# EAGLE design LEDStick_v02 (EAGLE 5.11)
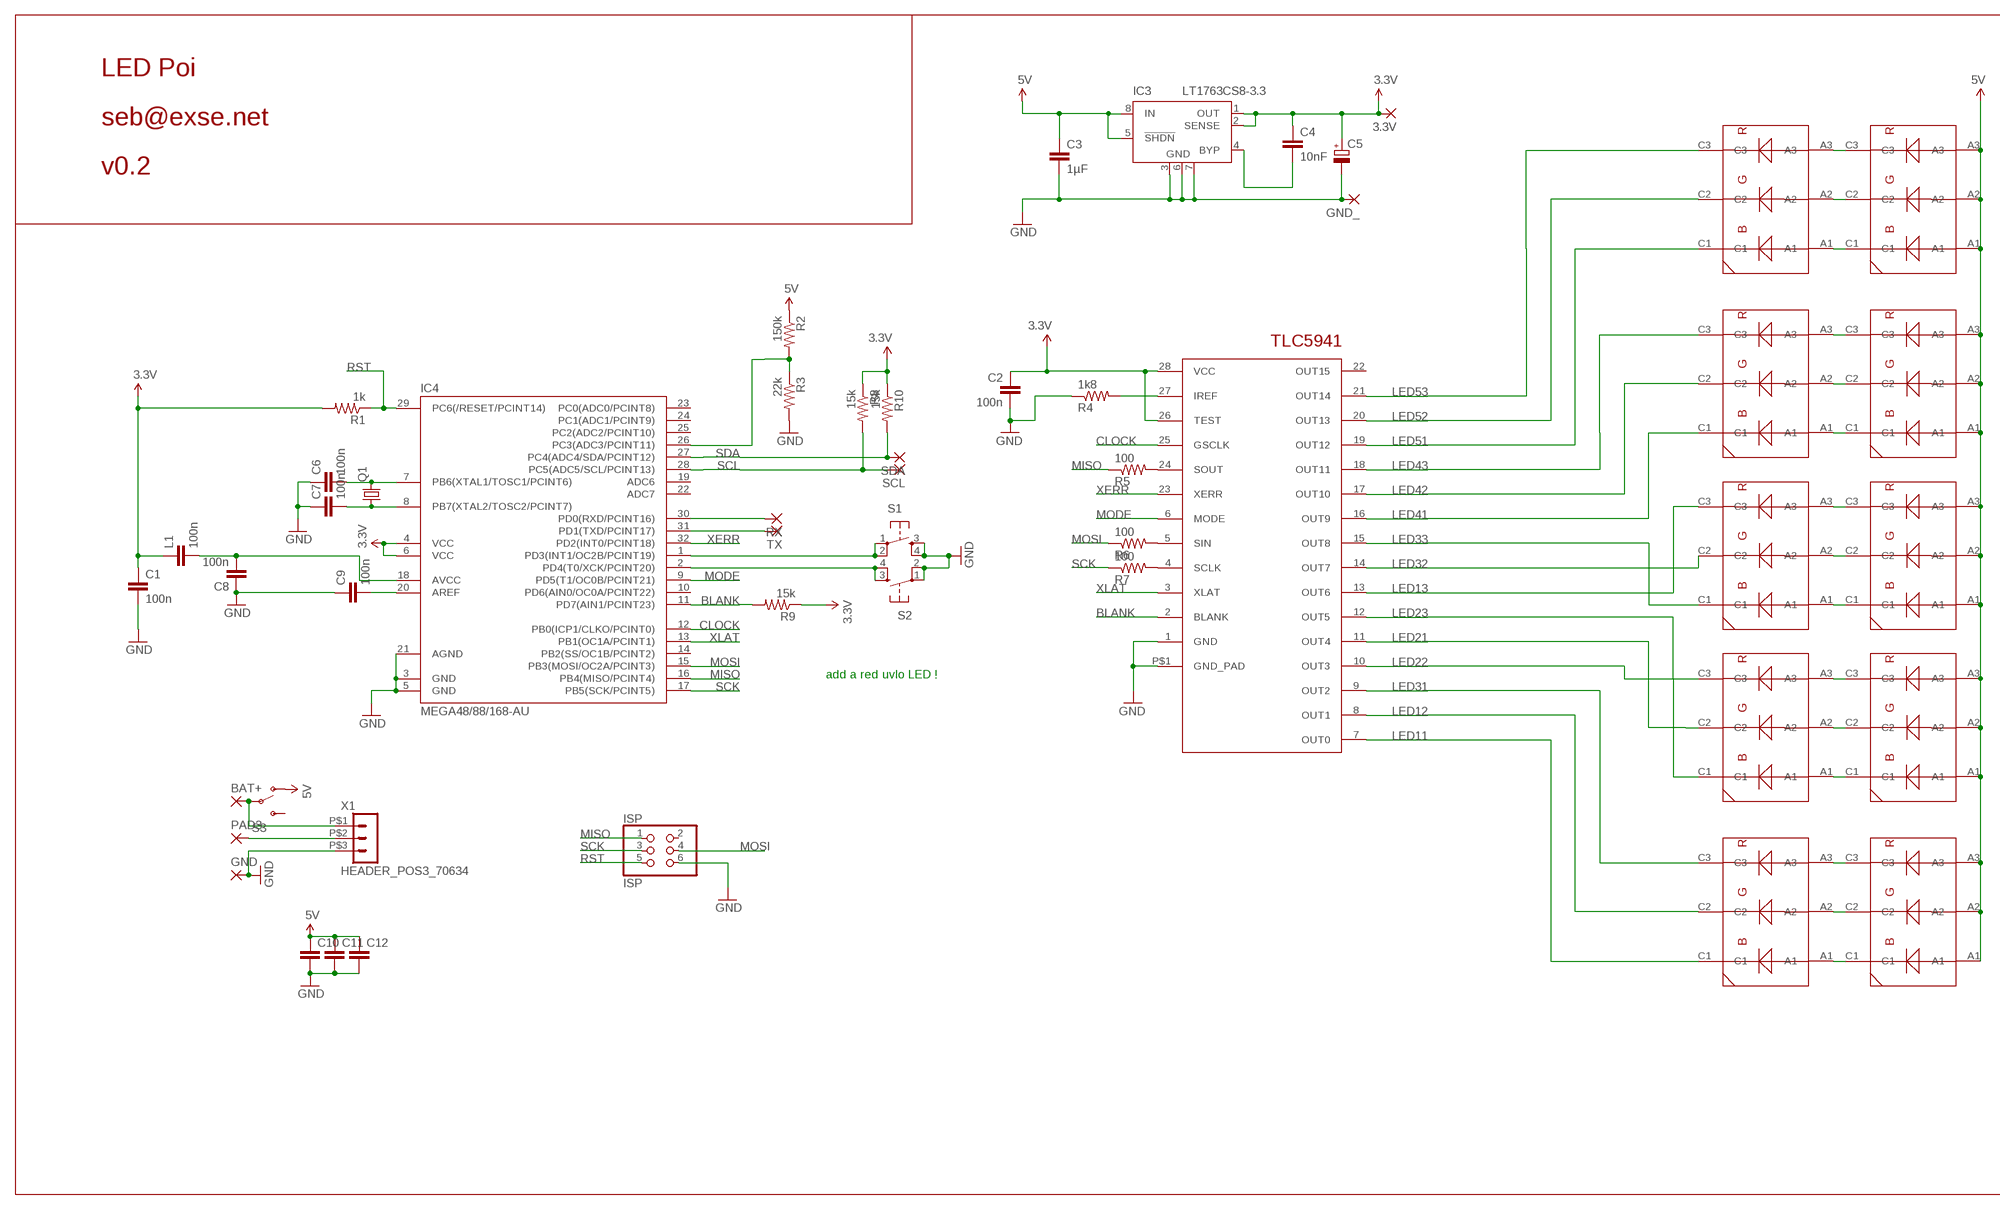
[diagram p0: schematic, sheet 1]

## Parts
3.3V  SMD2  [SMD1,27-2,54]
BAT+  SMD5  [SMD2,54-5,08]
C1  100n  CAP0805  [0805]
C2  100n  CAP0805  [0805]
C3  1µF  CAP0805  [0805]
C4  10nF  CAP0805  [0805]
C5  CPOL-EUSMCC  [SMC_C]
C6  100n  CAP0805  [0805]
C7  100n  CAP0805  [0805]
C8  100n  CAP0805  [0805]
C9  100n  CAP0805  [0805]
C10  C-EUC1210K  [C1210K]
C11  C-EUC1210K  [C1210K]
C12  C-EUC1210K  [C1210K]
D1  OSRAM_LRTB_GFTGSMALL  [PLCC-6_SMALL]
D2  OSRAM_LRTB_GFTGSMALL  [PLCC-6_SMALL]
D3  OSRAM_LRTB_GFTGSMALL  [PLCC-6_SMALL]
D4  OSRAM_LRTB_GFTGSMALL  [PLCC-6_SMALL]
D5  OSRAM_LRTB_GFTGSMALL  [PLCC-6_SMALL]
D6  OSRAM_LRTB_GFTGSMALL  [PLCC-6_SMALL]
D7  OSRAM_LRTB_GFTGSMALL  [PLCC-6_SMALL]
D8  OSRAM_LRTB_GFTGSMALL  [PLCC-6_SMALL]
D9  OSRAM_LRTB_GFTGSMALL  [PLCC-6_SMALL]
D10  OSRAM_LRTB_GFTGSMALL  [PLCC-6_SMALL]
GND  SMD5  [SMD2,54-5,08]
GND_  SMD2  [SMD1,27-2,54]
IC2  TLC5941  [SSOP28]
IC3  LT1763CS8-3.3  [SOIC8]
IC4  MEGA48/88/168-AU  [TQFP32-08]
ISP  ISP  PINHD-2X03_2.54  [2X03]
L1  100n  CAP0805  [0805]
PAD3  SMD5  [SMD2,54-5,08]
Q1  X22-OSCILLATOR  [X22]
R1  1k  RESISTOR  [0805]
R2  150k  RESISTOR  [0805]
R3  22k  RESISTOR  [0805]
R4  1k8  RESISTOR  [0805]
R5  100  RESISTOR  [0805]
R6  100  RESISTOR  [0805]
R7  100  RESISTOR  [0805]
R8  15k  RESISTOR  [0805]
R9  15k  RESISTOR  [0805]
R10  15k  RESISTOR  [0805]
RX  SMD2  [SMD1,27-2,54]
S1  LSH  [LSH]
S2  LSH  [LSH]
S3  SWITCH-SPSTPTH_LOCK  [SWITCH-SPDT_LOCK.007S]
SCL  SMD2  [SMD1,27-2,54]
SDA  SMD2  [SMD1,27-2,54]
TX  SMD2  [SMD1,27-2,54]
X1  HEADER_POS3_70634  [70634-POS3]

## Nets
3.3V: 3.3V.1(P) C1.1 C2.1 C4.1 C5.+ IC2.26(TEST) IC2.28(VCC) IC3.1(OUT) IC3.2(SENSE) IC4.4(VCC) IC4.6(VCC) L1.1 R1.2 R8.1 R9.1 R10.1
5V: C3.1 C10.1 C11.1 C12.1 D1.A1 D1.A2 D1.A3 D3.A1 D3.A2 D3.A3 D5.A1 D5.A2 D5.A3 D7.A1 D7.A2 D7.A3 D9.A1 D9.A2 D9.A3 IC3.5(!SHDN) IC3.8(IN) R2.1 S3.1(O)
BLANK: IC2.2(BLANK) IC4.11(PD7(AIN1/PCINT23)) R9.2
CLOCK: IC2.25(GSCLK) IC4.12(PB0(ICP1/CLKO/PCINT0))
GND: C1.2 C2.2 C3.2 C5.- C6.1 C7.1 C8.1 C9.1 C10.2 C11.2 C12.2 GND.1(P) GND_.1(P) IC2.1(GND) IC2.P$1(GND_PAD) IC3.3(GND) IC3.6(GND) IC3.7(GND) IC4.3(GND) IC4.5(GND) IC4.21(AGND) ISP.6 R3.2 R4.1 S1.3 S1.4 S2.1 S2.2 X1.P$3
LED11: D10.C1 IC2.7(OUT0)
LED12: D10.C2 IC2.8(OUT1)
LED13: D6.C3 IC2.13(OUT6)
LED21: D8.C2 IC2.11(OUT4)
LED22: D8.C3 IC2.10(OUT3)
LED23: D8.C1 IC2.12(OUT5)
LED31: D10.C3 IC2.9(OUT2)
LED32: D6.C2 IC2.14(OUT7)
LED33: D6.C1 IC2.15(OUT8)
LED41: D4.C1 IC2.16(OUT9)
LED42: D4.C2 IC2.17(OUT10)
LED43: D4.C3 IC2.18(OUT11)
LED51: D2.C1 IC2.19(OUT12)
LED52: D2.C2 IC2.20(OUT13)
LED53: D2.C3 IC2.21(OUT14)
MISO: IC4.16(PB4(MISO/PCINT4)) ISP.1 R5.1
MODE: IC2.6(MODE) IC4.9(PD5(T1/OC0B/PCINT21))
MOSI: IC4.15(PB3(MOSI/OC2A/PCINT3)) ISP.4 R6.1
N$1: IC2.24(SOUT) R5.2
N$2: C4.2 IC3.4(BYP)
N$3: C6.2 IC4.7(PB6(XTAL1/TOSC1/PCINT6)) Q1.3
N$4: IC2.5(SIN) R6.2
N$5: IC2.4(SCLK) R7.2
N$6: C7.2 IC4.8(PB7(XTAL2/TOSC2/PCINT7)) Q1.1
N$7: D1.C3 D2.A3
N$8: D1.C2 D2.A2
N$9: D1.C1 D2.A1
N$10: D3.C3 D4.A3
N$11: D3.C2 D4.A2
N$12: D3.C1 D4.A1
N$13: IC2.27(IREF) R4.2
N$14: D5.C3 D6.A3
N$15: D5.C2 D6.A2
N$16: D5.C1 D6.A1
N$17: D7.C3 D8.A3
N$18: D7.C2 D8.A2
N$19: D7.C1 D8.A1
N$20: D9.C3 D10.A3
N$21: D9.C2 D10.A2
N$22: D9.C1 D10.A1
N$23: IC4.1(PD3(INT1/OC2B/PCINT19)) S1.1 S1.2
N$24: IC4.2(PD4(T0/XCK/PCINT20)) S2.3 S2.4
N$25: IC4.26(PC3(ADC3/PCINT11)) R2.2 R3.1
N$26: BAT+.1(P) S3.2(P) X1.P$1
N$27: C8.2 IC4.18(AVCC) L1.2
N$28: C9.2 IC4.20(AREF)
N$29: PAD3.1(P) X1.P$2
N$31: IC4.30(PD0(RXD/PCINT16)) RX.1(P)
N$32: IC4.31(PD1(TXD/PCINT17)) TX.1(P)
RST: IC4.29(PC6(/RESET/PCINT14)) ISP.5 R1.1
SCK: IC4.17(PB5(SCK/PCINT5)) ISP.3 R7.1
SCL: IC4.28(PC5(ADC5/SCL/PCINT13)) R8.2 SCL.1(P)
SDA: IC4.27(PC4(ADC4/SDA/PCINT12)) R10.2 SDA.1(P)
XERR: IC2.23(XERR) IC4.32(PD2(INT0/PCINT18))
XLAT: IC2.3(XLAT) IC4.13(PB1(OC1A/PCINT1))
Unconnected: IC2.22(OUT15) IC4.10(PD6(AIN0/OC0A/PCINT22)) IC4.14(PB2(SS/OC1B/PCINT2)) IC4.19(ADC6) IC4.22(ADC7) IC4.23(PC0(ADC0/PCINT8)) IC4.24(PC1(ADC1/PCINT9)) IC4.25(PC2(ADC2/PCINT10)) ISP.2 S3.3(S)

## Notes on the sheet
- LED Poi
- seb@exse.net
- v0.2
- add a red uvlo LED !

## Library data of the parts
3.3V GND_ RX SCL SDA TX = wirepad:SMD2: SMD PAD
BAT+ GND PAD3 = wirepad:SMD5: SMD PAD
C1-C4 C6-C9 L1 = SparkFun:CAP: Capacitor
C5 = resistor:CPOL-EU: POLARIZED CAPACITOR, European symbol
C10-C12 = rcl:C-EU: CAPACITOR, European symbol
D1-D10 = seb:OSRAM_LRTB_GFTG
IC2 = tlc:TLC5941
IC3 = linear-technology:LT1763CS8: 500mA, Low Noise, LDO Micropower Regulators Source: http://cds.linear.com/docs/Datasheet/1763ff.pdf
IC4 = avr-7:MEGA48/88/168
ISP = pinhead-2:PINHD-2X03: PIN HEADER
Q1 = seb:X22-OSCILLATOR
R1-R10 = SparkFun:RESISTOR: Resistor
S1 S2 = switch-tact:LSH
S3 = SparkFun:SWITCH-SPST: SPST Switch Simple slide switch. Spark Fun Electronics SKU : COM-00102
X1 = con-molex-c-grid-sl:HEADER_POS3_?: Molex -C-Grid® / SL Series connector Wire-to-Board 2.54 mm (0.100") pitch header, 3 positions.

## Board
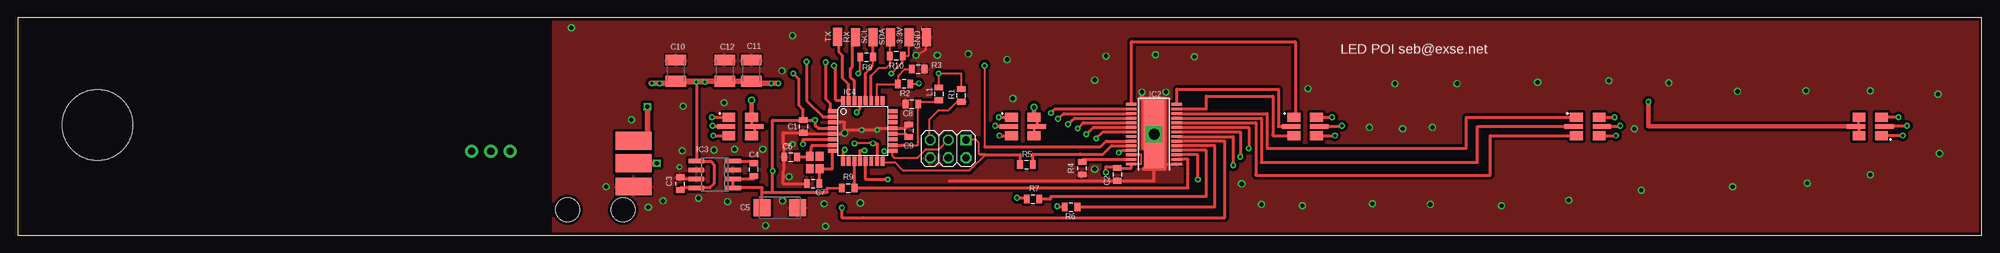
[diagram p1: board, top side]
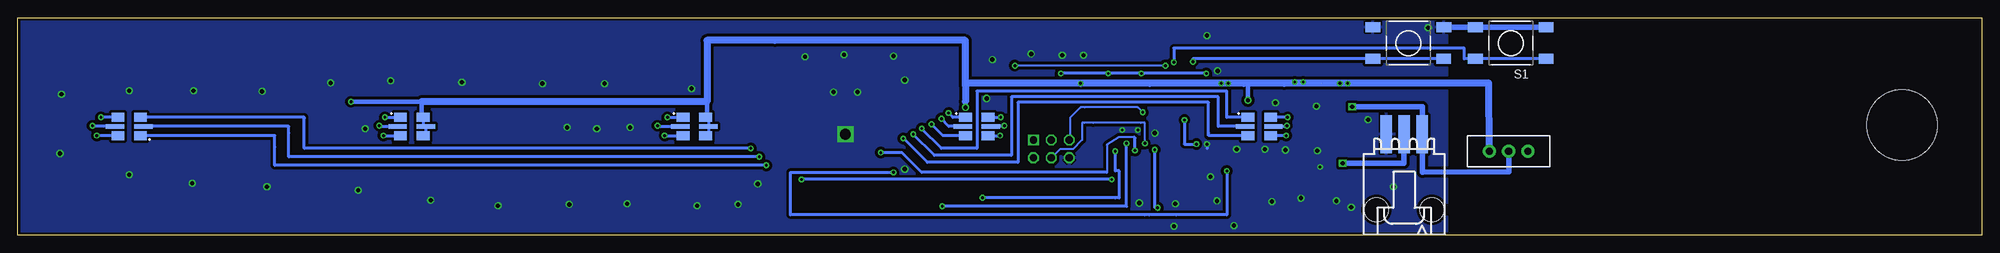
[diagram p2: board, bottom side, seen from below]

Size 278.1 x 30.8 mm. Coordinates in mm from the lower left corner, seen from the top.
Outline: 278.1,30.8 0,30.8 0,0 278.1,0 278.1,30.8
Copper layers (1*16): Top 0.035mm / dielectric 1.5mm / Bottom 0.035mm
Design rules "default *": minimum track width 10mil, minimum drill 0.4mm, track to track 8mil, track to pad 8mil, pad to pad 8mil, via to via 8mil, smd to smd 8mil, copper to edge 8mil, drill to drill 8mil, minimum pad ring 10mil, minimum via ring 8mil, stop-mask expansion 4mil, vias tented up to drill 100mil, thermal gap 10mil
Holes 10 mm at 11.3,15.6

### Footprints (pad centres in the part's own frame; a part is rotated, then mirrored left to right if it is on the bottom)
SMD1,27-2,54 = smd 1.27 x 2.54: 1 0,0
SMD2,54-5,08 = smd 2.54 x 5.08: 1 0,0
0805 = smd 0.8 x 1.2: 1 -0.9,0; 2 0.9,0
SMC_C = smd 2.4 x 2.4: + -2.5,0; - 2.5,0
C1210K = smd 1.5 x 2.9: 1 -1.5,0; 2 1.5,0
PLCC-6_SMALL = smd 1.3 x 1.8: A1 1.3,-1.6; A3 -1.3,-1.6; C1 1.3,1.6; C3 -1.3,1.6 | smd 0.6 x 2.6: A2 0,-2; C2 0,2
SSOP28 = smd 0.4 x 1.5: 1 -4.225,-3.225; 2 -3.575,-3.225; 3 -2.925,-3.225; 4 -2.275,-3.225; 5 -1.625,-3.225; 6 -0.975,-3.225; 7 -0.325,-3.225; 8 0.325,-3.225; 9 0.975,-3.225; 10 1.625,-3.225; 11 2.275,-3.225; 12 2.925,-3.225; 13 3.575,-3.225; 14 4.225,-3.225; 15 4.225,3.225; 16 3.575,3.225; 17 2.925,3.225; 18 2.275,3.225; 19 1.625,3.225; 20 0.975,3.225; 21 0.325,3.225; 22 -0.325,3.225; 23 -0.975,3.225; 24 -1.625,3.225; 25 -2.275,3.225; 26 -2.925,3.225; 27 -3.575,3.225; 28 -4.225,3.225 | smd 9.7 x 2.8: P$1 0,0
SOIC8 = smd 0.6 x 2.2: 1 -1.905,-2.6; 2 -0.635,-2.6; 3 0.635,-2.6; 4 1.905,-2.6; 5 1.905,2.6; 6 0.635,2.6; 7 -0.635,2.6; 8 -1.905,2.6
TQFP32-08 = smd 1.27 x 0.559: 1 -4.293,2.8; 2 -4.293,2; 3 -4.293,1.2; 4 -4.293,0.4; 5 -4.293,-0.4; 6 -4.293,-1.2; 7 -4.293,-2; 8 -4.293,-2.8; 17 4.293,-2.8; 18 4.293,-2; 19 4.293,-1.2; 20 4.293,-0.4; 21 4.293,0.4; 22 4.293,1.2; 23 4.293,2; 24 4.293,2.8 | smd 0.559 x 1.27: 9 -2.8,-4.293; 10 -2,-4.293; 11 -1.2,-4.293; 12 -0.4,-4.293; 13 0.4,-4.293; 14 1.2,-4.293; 15 2,-4.293; 16 2.8,-4.293; 25 2.8,4.293; 26 2,4.293; 27 1.2,4.293; 28 0.4,4.293; 29 -0.4,4.293; 30 -1.2,4.293; 31 -2,4.293; 32 -2.8,4.293
2X03 = drill 1.016 square: 1 -2.54,-1.27 | drill 1.016 octagon: 2 -2.54,1.27; 3 0,-1.27; 4 0,1.27; 5 2.54,-1.27; 6 2.54,1.27
X22 = smd 1.3 x 1.1: 1 0.9,0.7; 2 -0.9,0.7; 3 -0.9,-0.7; 4 0.9,-0.7
LSH = smd 2.1 x 1.4: 1 -5.005,2.24; 2 5.015,2.24; 3 -5.005,-2.24; 4 5.005,-2.24
SWITCH-SPDT_LOCK.007S = drill 1.016 pad 1.88 round: 1 0,2.718; 2 0,0; 3 0,-2.718
70634-POS3 = smd 1.651 x 5.334: P$1 -2.54,0; P$2 0,0; P$3 2.54,0 | hole 3.404: -3.937,10.693; 3.937,10.693

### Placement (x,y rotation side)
3.3V  126.2,28 0 top
BAT+  87.2,13.4 90 top
C1  111.23,15.41 270 top
C2  155.71,8.61 270 top
C3  93.8,7.3 90 top
C4  104.2,9.3 90 top
C5  107.9,3.9 0 top
C6  109.45,11.11 0 top
C7  112.61,7.3 0 top
C8  126.6,18.6 0 top
C9  126.2,14.8 270 top
C10  93.2,23.3 90 top
C11  103.9,23.3 90 top
C12  100.1,23.3 90 top
D1  102.3,15.4 90 top
D2  102.3,15.4 90 bottom
D3  142.3,15.4 90 top
D4  142.3,15.4 90 bottom
D5  182.3,15.4 90 bottom
D6  182.3,15.4 90 top
D7  222.3,15.4 90 bottom
D8  222.3,15.4 90 top
D9  262.3,15.4 270 top
D10  262.3,15.4 270 bottom
GND  87.2,6.9 90 top
GND_  128.7,28 0 top
IC2  160.9,14.3 90 top
IC3  98.7,8.6 90 top
IC4  119.66,14.77 0 top
ISP  131.75,12.22 180 top
L1  130.4,20 270 top
PAD3  87.2,10.2 90 top
Q1  112.85,10.3 270 top
R1  133.59,19.79 90 top
R2  125.5,21.4 180 top
R3  127.5,23.5 0 top
R4  150.7,9.49 90 top
R5  142.82,10 0 top
R6  149.15,4.03 0 top
R7  143.75,5.15 0 top
R8  120.2,25.2 0 top
R9  117.6,6.7 0 top
R10  124.4,25.4 180 top
RX  118.6,28 0 top
S1  66.7,27.2 180 bottom
S2  81.2,27.2 0 bottom
S3  67,11.9 90 bottom
SCL  121.1,28 0 top
SDA  123.6,28 0 top
TX  116.1,28.1 0 top
X1  81.8,14.3 180 bottom

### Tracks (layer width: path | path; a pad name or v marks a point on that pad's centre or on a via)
3.3V  (via drill 0.4)
  Top 0.305: IC2.26 159.1,11.38 159.1,10.1 157.68,10.1 IC2.28 | R1.2 133.59,22.9 v130.4,22.9 | 130.59,22.9 130.5,22.9 130.59,22.9 | v130.4,22.9 130.59,22.9 | v130.4,22.9 L1.1 | v130.4,22.9 130.59,22.9 | v123.7,22.9 125,24.2 125.3,24.5 R10.1 126.1,25.4 126.2,25.5 3.3V.1 | v119,22.9 119.3,23.2 R8.1
  Top 0.406: IC2.28 157.68,9.51 C2.1 155.71,9.7 154.1,9.7 v154.1,8.9 | C1.1 106.9,16.31 106.9,6.1 | 106.9,6.1 v106.9,9.1 | 106.9,6.1 v106.9,9.1 | v130.4,22.9 130.59,22.9 | 130.59,22.9 130.5,22.9 130.59,22.9 | 109.83,22.9 v109.8,22.9 110.6,22.1 110.6,18.4 111.23,17.77 C1.1 | R9.1 114.63,6.68 114.63,6.08 106.9,6.1 | 106.9,6.1 v106.9,9.1 | C4.1 104.2,7.96 IC3.2 IC3.1 105.4,6.7 105.4,6.1 | 105.4,6.1 C5.+ 105.4,6.1 | 105.4,6.1 106.9,6.1 | C1.1 111.8,16.31 | 111.8,16.31 v112.9,16.31 | v112.9,16.31 112.9,15.5 113.3,15.17 113.44,15.17 IC4.4 | v111.2,12.9 111.2,13.49 | 111.2,13.49 111.2,13.57 | 111.8,16.31 v112.9,16.31 | IC4.6 113.44,13.57 111.2,13.57 | 111.2,13.49 111.2,13.57
  Bottom 0.305: 118.6,22.9 v119,22.9 | v123.7,22.9 123.5,22.9
  Bottom 0.406: v154.1,8.9 168.7,8.9 168.7,6.5 168.7,2.9 117.9,2.9 | 117.9,2.9 114.1,2.9 106.9,2.9 v106.9,9.1 | 117.9,2.9 118.5,2.9 | v109.8,22.9 118.6,22.9 | 118.6,22.9 v119,22.9 | 118.6,22.9 v119,22.9 | 118.6,22.9 v119,22.9 | v119,22.9 v123.7,22.9 123.5,22.9 v130.4,22.9 | v111.2,12.9 112.9,12.9 v112.9,16.31
5V  (via drill 0.4, 0.6)  (1 unrouted)
  Top 0.305: R2.1 127.6,21.4 v127.6,21.5
  Top 0.406: 260.7,15.4 D9.A1 | 260.7,15.4 D9.A2 260.7,15.4 | 260.7,15.4 D9.A3 | D1.A3 104.3,14.1 D1.A2 | D1.A2 103.9,15.4 D1.A1 | D1.A2 104.5,15.4 | D3.A3 143.9,15.4 D3.A2 144.3,16.7 D3.A1 | C3.1 93.8,6.7 IC3.8 98,6.7 98.6,7.3 98.6,10 98.3,10.3 98.09,10.51 IC3.5 v96.1,21.7
  Top 0.61: D9.A2 230.9,15.4 v230.9,18.9 | v103.9,19.1 103.9,17.9 D1.A1 | v143.9,18.1 D3.A1 | v96.1,21.7 96.1,21.6
  Top 0.813: v106.7,21.5 103.9,21.5 C11.1 C12.1 C10.1 93.2,21.5 93.5,21.5 93.5,21.7 v96.1,21.7 v97.3,21.7 | v106.7,21.5 v107.7,21.5 v106.7,21.5 | v89.8,21.5 89.7,21.5 89.7,21.51 | v89.8,21.5 v90.9,21.5 | v90.9,21.5 93.5,21.5 | v89.8,21.5 v90.9,21.5
  Bottom 0.406: D5.A1 180.3,16.7 D5.A2 180.3,14.1 D5.A3 | D7.A3 220.3,14.1 D7.A2 220.7,15.4 D7.A1 | v96.1,21.7 100.5,21.7 98.8,21.5
  Bottom 0.61: v230.9,18.9 220.9,18.9 220.9,16.7 D7.A1 | 117.8,21.5 v127.6,21.5 | 180.3,16.7 180.5,16.7 180.5,18.9 | 143.9,18.9 v143.9,18.1 | 104.5,21.5 103.9,21.5 v103.9,19.1
  Bottom 1.016: 220.9,18.9 180.5,18.9 180.5,27.6 170.9,27.6 143.9,27.6 143.9,21.2 | 143.9,21.2 143.9,21.5 v127.6,21.5 117.8,21.5 104.5,21.5 98.8,21.5 69.8,21.52 S3.1 | 143.9,21.2 143.9,18.9
BLANK
  Top 0.406: IC2.2 165.7,10.72 165.7,8.7 165.7,6.7 137.5,6.7 R9.2 | R9.2 118.46,6.7 R9.2 | IC4.11 118.5,10.48 R9.2
CLOCK  (via drill 0.4)
  Top 0.406: IC2.25 156.3,12.03 v155.9,11.7 | v119.9,12 119.26,12 IC4.12
  Bottom 0.305: 123.9,8.9 123.9,12.8 122.2,13.9 120,13.9 119.9,13.8
  Bottom 0.406: v155.9,11.7 152.9,11.7 150.1,8.9 123.9,8.9 | v119.9,12 119.9,13.8 120,13.9
GND  (via drill 0.4, 0.6, 1.5)
  Top 0.305: 125.8,15.17 C9.1 | v127.2,25.46 128.6,26.27 GND_.1
  Top 0.406: IC2.1 160.9,10.07 IC2.P$1 160.9,7.71 C2.2 131.89,7.71 | C7.1 108.4,7.3 C6.1 108.4,14.51 | 108.4,14.51 C1.2 111.63,14.37 IC4.5 117.1,14.37 v117.1,14.46 | IC3.7 94.2,7.96 C3.2 | 108.4,14.51 108.4,12.9 v109.7,12.9 | IC4.3 117.1,15.97 v117.1,14.46 | v117.1,14.46 117.1,14.9 v119.5,14.9 v121.7,14.9 121.7,15.17 IC4.21 125.8,15.17
  Top 0.61: 159.5,9.4 162.4,9.4 162.4,19.3 159.4,19.3 | 159.4,19.3 159.4,12.3 | v159.2,20.27 159.2,19.3 159.4,19.3
  Bottom 0.406: v109.7,12.9 109.7,12.27
  Bottom 0.813: S2.2 S1.4 S1.3
  other vias: 93.7,9.66 101.5,12.16 105.9,1.36 100.5,4.76 109.2,8.27 100,18.77 114.2,4.46 166.6,25.27 161.1,25.57 154.1,25.36 140.9,19.36 162.6,20.27 152.5,9.37 182.7,20.77 195,21.46 203.8,21.46 215.2,21.66 225.3,21.86 233.8,21.57 243.5,20.36 253.2,20.46 262.3,20.46 271.9,19.96 272.1,11.56 262.3,8.56 253.4,7.37 242.8,6.87 229.9,6.37 219.6,4.96 210.1,4.17 200,4.37 191.8,4.46 181.9,4.17 176.1,4.37 191.4,15.27 196.1,15.06 200.3,15.27 228.9,15.06 134.6,25.66 130.2,25.46 109.7,28.27 108.2,23.27 105.5,12.16 108.3,4.87 119.3,4.57 114.4,1.26 173.3,7.26 152.5,21.96 140.1,24.86 83.3,6.87 94.2,18.27 89.3,3.96 91.4,4.87 98.6,12.06 96.4,5.26 94.1,11.96 160.9,14.3 78.4,29.36 86.9,16.36
  pour Bottom (isolate 0.406): 75.8,0.1 278.1,0 278.2,30.8 75.8,30.9
  pour Top (isolate 0.406): 75.8,0.1 278.2,0 278.2,30.8 75.8,30.9
LED11  (via drill 0.4)
  Top 0.406: IC2.7 172.1,13.97 v172.1,9.9
  Bottom 0.406: v172.1,9.9 241.7,9.9 241.7,12.5 241.7,14.1 D10.C1
LED12  (via drill 0.4)
  Top 0.406: IC2.8 173.1,14.62 v173.1,11.1
  Bottom 0.406: v173.1,11.1 239.7,11.1 239.7,14.5 239.7,15.4 D10.C2
LED13
  Top 0.406: IC2.13 168.3,17.88 168.3,19.7 177.7,19.7 177.7,14.3 177.7,14.1 D6.C3
LED21
  Top 0.406: IC2.11 176.1,16.57 176.1,10.3 204.9,10.3 206.7,10.3 206.7,15.4 D8.C2
LED22
  Top 0.406: IC2.10 175.3,15.93 175.3,8.5 208.5,8.5 208.5,14.1 D8.C3
LED23
  Top 0.406: IC2.12 176.9,17.23 176.9,12.3 205.1,12.3 205.1,12.5 205.1,16.7 D8.C1
LED31  (via drill 0.4)
  Top 0.406: IC2.9 174.3,15.28 v174.3,12.3
  Bottom 0.406: v174.3,12.3 237.5,12.3 237.5,16.5 237.5,16.7 D10.C3
LED32
  Top 0.406: IC2.14 164.12,20.7 178.5,20.7 178.5,15.4 D6.C2
LED33
  Top 0.406: IC2.15 157.7,18.52 157.7,27.4 180.9,27.4 180.9,16.7 D6.C1
LED41  (via drill 0.4)
  Top 0.406: v146.3,17.3 146.9,17.88 IC2.16
  Bottom 0.406: D4.C1 145.7,16.7 v146.3,17.3
LED42  (via drill 0.4)
  Top 0.406: v147.3,16.5 148.1,17.23 IC2.17
  Bottom 0.406: D4.C2 146.3,15.4 v147.3,16.5
LED43  (via drill 0.4)
  Top 0.406: v148.7,15.7 149.7,16.57 IC2.18
  Bottom 0.406: D4.C3 147.1,14.1 v148.7,15.7
LED51  (via drill 0.4)
  Top 0.406: IC2.19 150.9,15.93 v150.1,15.1
  Bottom 0.406: v150.1,15.1 147.3,12.3 142.3,12.3 142.3,20.4 106.9,20.4 106.9,16.9 106.9,16.7 D2.C1
LED52  (via drill 0.4)
  Top 0.406: IC2.20 152.3,15.28 v151.3,14.3
  Bottom 0.406: v151.3,14.3 148.3,11.3 137.4,11.3 137.4,19.6 108.1,19.6 108.1,16.1 108.1,15.4 D2.C2
LED53  (via drill 0.4)
  Top 0.406: IC2.21 153.7,14.62 v152.7,13.7
  Bottom 0.406: v152.7,13.7 149.3,10.3 136.5,10.3 136.5,18.8 109.5,18.8 109.5,14.5 109.5,14.1 D2.C3
MISO
  Top 0.305: ISP.1 135.7,13.49 136.1,13.1 136.1,11.5 136.2,11.4 | 122.46,10.3 124.2,10.3 125.3,9.2 134.8,9.2 137,11.4
  Top 0.406: 136.2,11.4 137,11.4 141.93,11.4 R5.1 | IC4.16 122.46,10.3
MODE  (via drill 0.4)
  Top 0.406: IC2.6 170.9,13.32 170.9,4.5 170.9,2.5 119.7,2.5 116.86,2.5 116.7,2.5 v116.7,3.9 | 116.86,12.1 v117.1,12.1 116.86,12.1 | 116.86,12.1 IC4.9
  Bottom 0.406: v116.7,3.9 117.1,3.9 v117.1,12.1
MOSI  (via drill 0.4)
  Top 0.305: v121.1,13 v118.5,13
  Top 0.406: R6.1 147.3,4.03 v147.2,4.1 | v121.1,13 121.66,13 IC4.15
  Bottom 0.305: v118.5,13 118.5,15.9 119.1,15.9 125.8,15.9 127.1,15.9 127.4,15.9 127.4,13.5 128.7,12.2 130.5,12.2 ISP.4
  Bottom 0.406: v147.2,4.1 121.1,4.1 v121.1,13
N$1
  Top 0.406: IC2.24 154.9,12.68 153.7,11.5 150.5,11.5 150.3,11.5 143.72,11.5 R5.2
N$2
  Top 0.406: IC3.4 104.2,10.51 C4.2
N$3
  Top 0.406: C6.2 111.8,11.1 Q1.3 112.5,12.77 IC4.7
N$4
  Top 0.406: IC2.5 169.5,12.68 169.5,5.7 169.5,4.03 R6.2
N$5
  Top 0.406: IC2.4 168.3,12.03 168.3,6.9 168.3,5.5 146.3,5.5 146.3,5.15 R7.2
N$6
  Top 0.406: 115.01,9.4 Q1.1 C7.2 | 115.01,9.4 115.37,9.4 | 115.37,9.4 IC4.8 | 115.01,9.4 115.37,9.4
N$7  (via drill 0.4)
  Top 0.406: v98.5,14.1 D2.A3
  Bottom 0.406: v98.5,14.1 D2.A3
N$8  (via drill 0.4)
  Top 0.406: D2.A2 98.5,15.4 v98.4,15.5
  Bottom 0.406: v98.4,15.5 98.4,15.4 D2.A2
N$9  (via drill 0.4)
  Top 0.406: v98.3,16.7 D2.A1
  Bottom 0.406: v98.3,16.7 D2.A1
N$10  (via drill 0.4)
  Top 0.406: v139,14.1 D4.A3
  Bottom 0.406: D4.A3 v139,14.1
N$11  (via drill 0.4)
  Top 0.406: v138.4,15.5 138.6,15.4 D4.A2
  Bottom 0.406: D4.A2 138.4,15.4 v138.4,15.5
N$12  (via drill 0.4)
  Top 0.406: v138.9,16.7 D4.A1
  Bottom 0.406: D4.A1 v138.9,16.7
N$13
  Top 0.406: IC2.27 150.7,10.72 R4.2
N$14  (via drill 0.4)
  Top 0.406: D6.A3 v186.5,14.1
  Bottom 0.406: v186.5,14.1 D6.A3
N$15  (via drill 0.4)
  Top 0.406: D6.A2 187.5,15.4 v187.5,15.5
  Bottom 0.406: v187.5,15.5 187.5,15.4 D6.A2
N$16  (via drill 0.4)
  Top 0.406: D6.A1 v186.1,16.7
  Bottom 0.406: v186.1,16.7 D6.A1
N$17  (via drill 0.4)
  Top 0.406: D8.A3 v226.3,14.1
  Bottom 0.406: v226.3,14.1 D8.A3
N$18  (via drill 0.4)
  Top 0.406: v226.9,15.5 226.8,15.4 D8.A2
  Bottom 0.406: D8.A2 226.9,15.4 v226.9,15.5
N$19  (via drill 0.4)
  Top 0.406: D8.A1 v226.1,16.7
  Bottom 0.406: v226.1,16.7 D8.A1
N$20  (via drill 0.4)
  Top 0.406: v266.3,16.7 D10.A3
  Bottom 0.406: D10.A3 v266.3,16.7
N$21  (via drill 0.4)
  Top 0.406: D10.A2 267.5,15.4 v267.5,15.5
  Bottom 0.406: v267.5,15.5 267.5,15.4 D10.A2
N$22  (via drill 0.4)
  Top 0.406: v266.9,14.1 D10.A1
  Bottom 0.406: D10.A1 v266.9,14.1
N$23  (via drill 0.4)
  Top 0.406: v114.4,24.5 114.4,19.3 115,18.7 115,17.94 115,17.57 IC4.1
  Bottom 0.406: S1.1 S1.2 73.3,24.96 73.3,26.5 114.4,26.5 v114.4,24.5 114.34,24.56
N$24  (via drill 0.4)
  Top 0.406: 111.7,23.6 111.7,19.07 114,16.77 IC4.2 | 111.7,23.6 v111.7,24.56 111.7,23.6
  Bottom 0.406: S2.4 S2.3 111.7,24.96 v111.7,24.56
N$25
  Top 0.305: 121.7,19.06 121.7,19.1 121.7,21.4 R2.2 124.7,21.4 124.7,22.6 125.6,23.5 R3.1
  Top 0.406: IC4.26 121.7,19.1
N$26  (via drill 0.6)
  Top 0.813: BAT+.1 89.16,13.4 v89.16,18.2
  Bottom 0.813: X1.P$1 79.56,14.3 79.2,14.3 | 79.2,18.2 v89.16,18.2 | 79.2,14.3 79.2,18.2 | S3.2 67,9 79.2,8.9 79.2,13.4 79.2,14.3 | 79.2,14.3 79.2,18.2
  Bottom 1.016: 79.56,14.3 X1.P$1
N$27
  Top 0.305: 125.33,12.77 127.47,12.77 127.5,13.3 127.5,13.6 C8.2 127.5,18.9 130.4,18.9 L1.2
  Top 0.406: IC4.18 125.33,12.77
N$28
  Top 0.305: 123.98,14.4 125.8,14.4 C9.2
  Top 0.406: 123.98,14.4 IC4.20
N$29  (via drill 0.6)
  Top 0.813: v90.5,10.2 PAD3.1
  Bottom 0.813: v90.5,10.2 81.8,10.2 X1.P$2
N$31
  Top 0.406: RX.1 118.2,27.6 118.2,25.9 118.2,23.9 117.9,23.6 117.9,22.4 118.46,21.84 IC4.30
N$32
  Top 0.406: TX.1 116.3,27.9 116.3,25.9 116.8,25.4 116.8,22.2 117.66,21.34 IC4.31
RST  (via drill 0.4)
  Top 0.305: v118.8,17.4 119.26,17.86 | 134.21,18.89 R1.1 132.99,18.89 131.8,17.7 131.01,17.7 130.4,17.7 129.1,16.4 129.1,13.61 ISP.5
  Top 0.406: 119.26,17.86 IC4.29
  Bottom 0.305: v118.8,17.4 119.5,18.1 127,18.1 127.6,18.1 129.1,16.6 129.1,13.61 ISP.5
SCK  (via drill 0.4)
  Top 0.305: 123.9,11.92 123.9,11.2 124.1,11 127.4,11 128.6,12.2 130.45,12.2 ISP.3
  Top 0.406: R7.1 142.75,5.3 v141.5,5.3 | v122.7,11.9 123.95,11.9 IC4.17 123.9,11.92
  Bottom 0.406: v141.5,5.3 122.7,5.3 122.1,5.3 122.1,9.1 122.7,9.1 v122.7,11.9
SCL
  Top 0.305: 120.06,22.96 120.9,23.8 121.1,24 R8.2
  Top 0.406: R8.2 SCL.1 | IC4.28 120.06,22.96
SDA
  Top 0.305: SDA.1 123.5,27.9 R10.2 123.5,24.2 123,23.7 121.96,23.7 120.86,22.6
  Top 0.406: IC4.27 120.86,22.6
XERR  (via drill 0.4)
  Top 0.305: v136.9,24 136.9,12.5
  Top 0.406: IC2.23 154.1,13.32 153.3,12.5 136.9,12.5 | v115.6,24 115.8,23.8 115.8,19.2 115.94,19.06 IC4.32
  Bottom 0.305: v115.6,24 v136.9,24
XLAT  (via drill 0.4)
  Top 0.406: IC2.3 167.1,11.38 v167.1,7.9 | v123.2,7.9 120.06,7.9 IC4.13
  Bottom 0.406: v123.2,7.9 v167.1,7.9

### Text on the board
tNames: LED POI seb@exse.net
tStop: + | -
